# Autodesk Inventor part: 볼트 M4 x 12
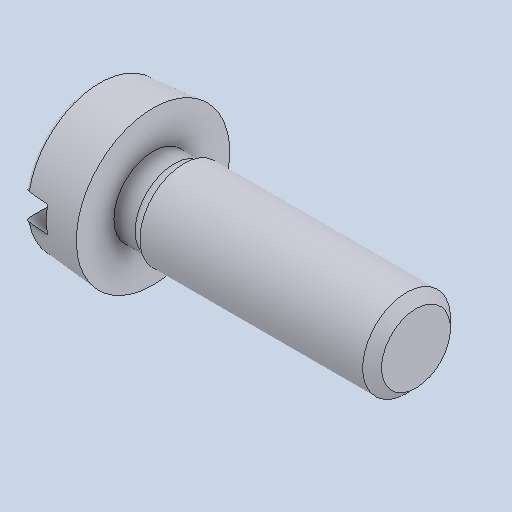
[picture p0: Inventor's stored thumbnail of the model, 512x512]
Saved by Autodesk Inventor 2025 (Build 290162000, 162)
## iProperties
Created: 2024-07
Part Number: 볼트 M4 x 12
Material: 강철, 연강
Description: 6각머리 태핑 나사
Document SubType Name: Modeling
Designer: deana
Density: 7.85 g/cm^3
Appearance: 기본값
Author: jhkim
Sending System: Autodesk Inventor 2025
Preprocessor: ST-DEVELOPER v20
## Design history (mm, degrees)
feature "Solid1"
node "솔리드1"
